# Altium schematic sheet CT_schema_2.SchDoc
size 271 x 273 mm
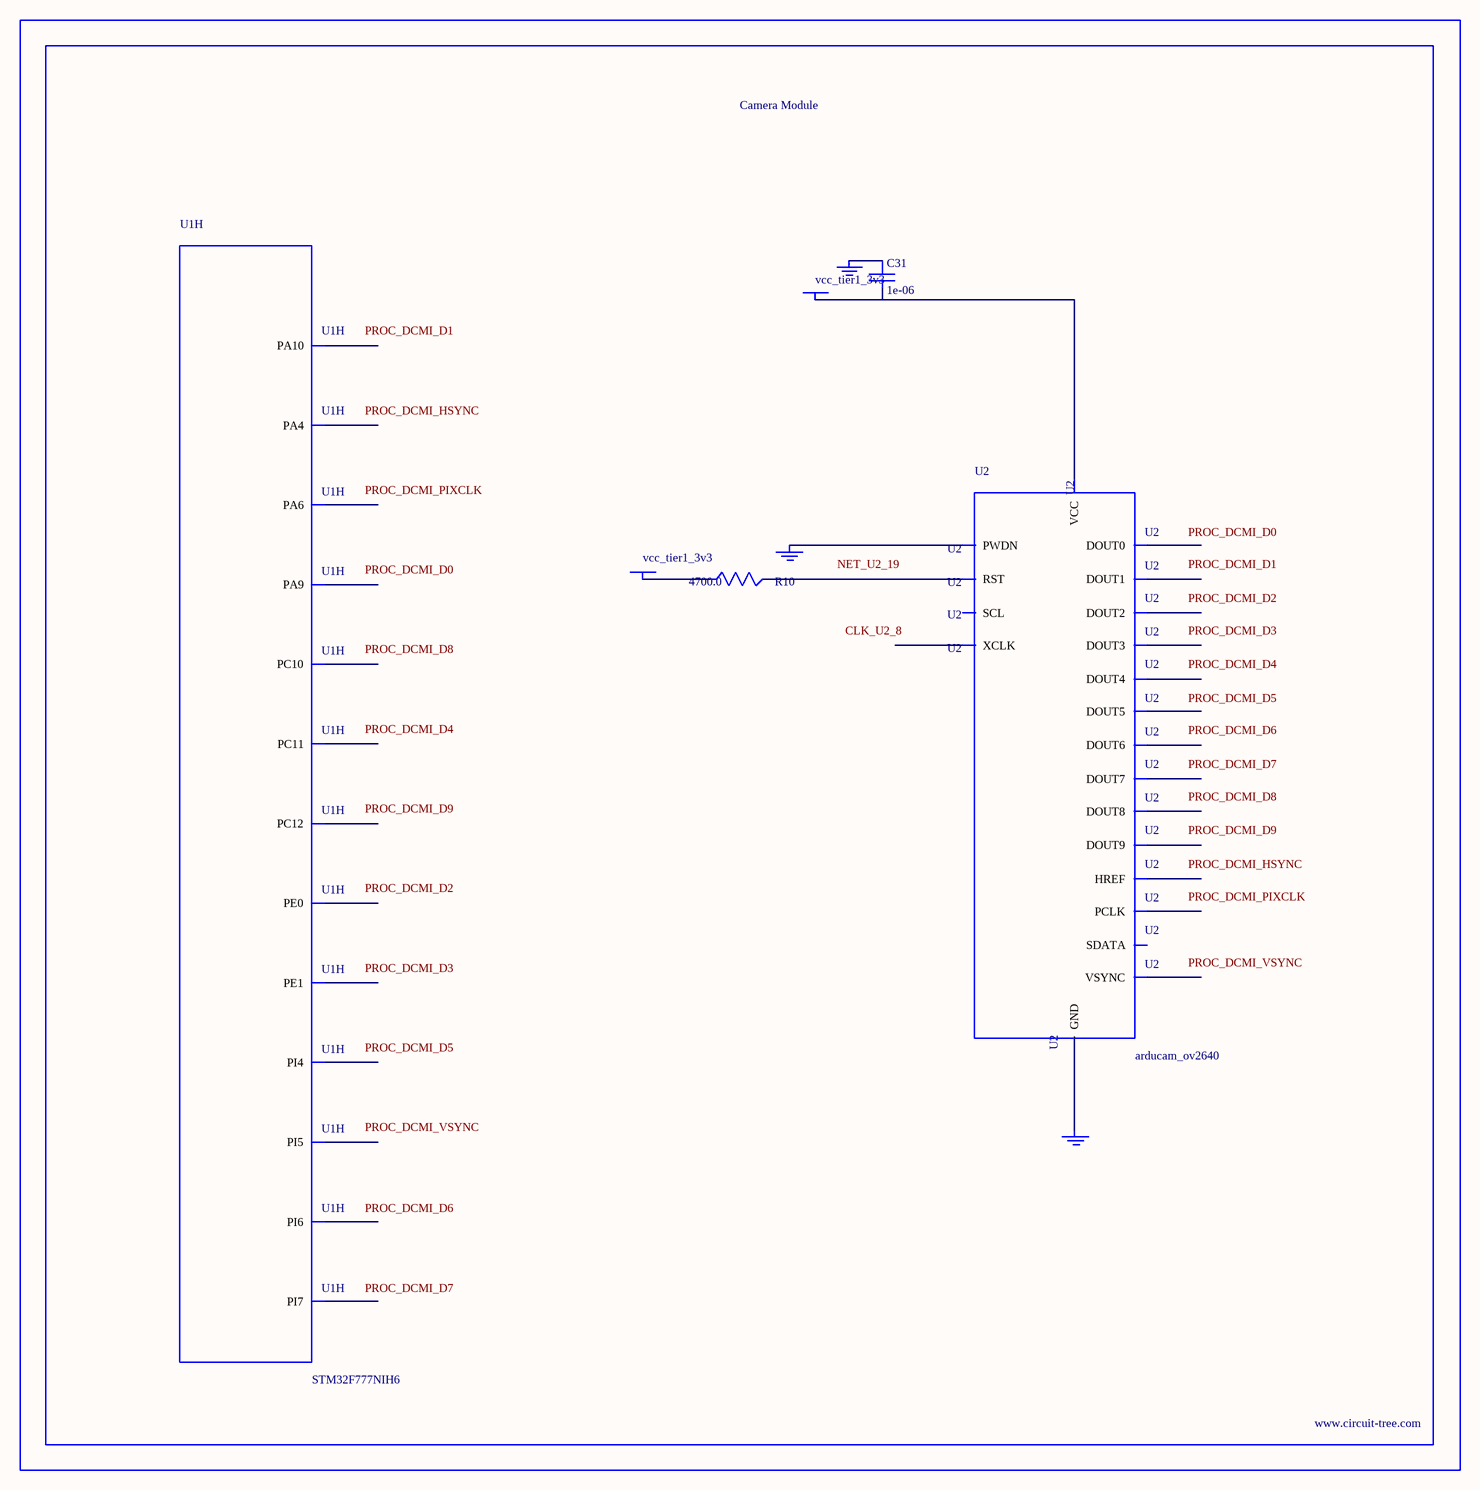
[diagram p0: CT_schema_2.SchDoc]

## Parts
BORDER1  (no value)
C31  1e-06  [C0603]
GND_INSTANCE_1_0  (no value)
GND_INSTANCE_1_1  (no value)
GND_INSTANCE_1_2  (no value)
POWER_INSTANCE_1_0  vcc_tier1_3v3
POWER_INSTANCE_1_1  vcc_tier1_3v3
R10  4700.0  [R0603]
U1  STM32F777NIH6  [TFBGA216]  (part H of 15)
U2  arducam_ov2640  [ARDUCAM]

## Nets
NetC31_1: C31.1 GND_INSTANCE_1_0.0(GND)
NetC31_2: C31.2 POWER_INSTANCE_1_0.0(PWR) U2.1(VCC)
NetGND_INSTANCE_1_1_0: GND_INSTANCE_1_1.0(GND) U2.20(PWDN)
NetGND_INSTANCE_1_2_0: GND_INSTANCE_1_2.0(GND) U2.2(GND)
NetPOWER_INSTANCE_1_1_0: POWER_INSTANCE_1_1.0(PWR) R10.1
NetR10_2: R10.2 U2.19(RST)

Not connected (* = marked no-connect by the designer): U1 A5(PE1) A6(PE0) A12(PC12) B13(PC11) B14(PC10) C3(PI4) D3(PI5) D4(PI7) D6(PI6) D15(PA10) E15(PA9) N4(PA4) P3(PA6); U2 3(SCL) 4(SDATA) 5(VSYNC) 6(HREF) 7(PCLK) 8(XCLK) 9(DOUT9) 10(DOUT8) 11(DOUT7) 12(DOUT6) 13(DOUT5) 14(DOUT4) 15(DOUT3) 16(DOUT2) 17(DOUT1) 18(DOUT0)

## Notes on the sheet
- Labels drawn without touching a wire or pin: CLK_U2_8, NET_U2_19, PROC_DCMI_D0, PROC_DCMI_D1, PROC_DCMI_D2, PROC_DCMI_D3, PROC_DCMI_D4, PROC_DCMI_D5, PROC_DCMI_D6, PROC_DCMI_D7, PROC_DCMI_D8, PROC_DCMI_D9, PROC_DCMI_HSYNC, PROC_DCMI_PIXCLK, PROC_DCMI_VSYNC

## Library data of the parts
BORDER1 = BORDER_PAGE1
C31 = C0603C105K3RACTU
GND_INSTANCE_1_0-GND_INSTANCE_1_2 = GND
POWER_INSTANCE_1_0 POWER_INSTANCE_1_1 = PWR
R10 = RC0603JR-074K7L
